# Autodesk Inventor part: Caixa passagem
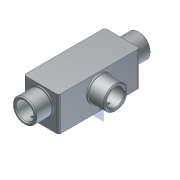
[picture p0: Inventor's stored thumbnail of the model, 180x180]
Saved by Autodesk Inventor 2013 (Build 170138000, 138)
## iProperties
Created: 2010-06
Part Number: Caixa passagem
Document SubType Name: Modeling
Designer: Usuario
Density: 1 g/cm^3
Material: Plástico PBT
Author: Usuario
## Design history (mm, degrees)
sketch "Sketch1"
  geometry: L1 (-20, 61.5)-(20, 61.5) reference; L2 (24.5, 57)-(24.5, -57) reference; L3 (20, -61.5)-(-20, -61.5) reference; L4 (-24.5, -57)-(-24.5, 57) reference; L5 (28, 61.5)-(28, -61.5) reference; L6 (-24.5, 65)-(24.5, 65) reference; L7 (-28, -61.5)-(-28, 61.5) reference; L8 (24.5, -65)-(-24.5, -65) reference; C1 r 2 at (-24.5, -61.5) reference; C2 r 2 at (24.5, -61.5) reference; C3 r 2 at (24.5, 61.5) reference; C4 r 2 at (-24.5, 61.5) reference; A1 r 4.5 centre (-24.5, 61.5) between (-24.5, 57) and (-20, 61.5) reference; A2 r 4.5 centre (24.5, 61.5) between (20, 61.5) and (24.5, 57) reference; A3 r 4.5 centre (24.5, -61.5) between (24.5, -57) and (20, -61.5) reference; A4 r 4.5 centre (-24.5, -61.5) between (-20, -61.5) and (-24.5, -57) reference; A5 r 3.5 centre (24.5, 61.5) between (28, 61.5) and (24.5, 65) reference; A6 r 3.5 centre (-24.5, 61.5) between (-24.5, 65) and (-28, 61.5) reference; A7 r 3.5 centre (-24.5, -61.5) between (-28, -61.5) and (-24.5, -65) reference; A8 r 3.5 centre (24.5, -61.5) between (24.5, -65) and (28, -61.5) reference; 1 further point
extrude "Extrusion1" new body sketch "Sketch1" distance "d0" = 55; taper "d1" = 0 deg
sketch "Sketch2"
  geometry: L1 (-20, 61.5)-(20, 61.5) reference; L2 (24.5, 57)-(24.5, -57) reference; L3 (20, -61.5)-(-20, -61.5) reference; L4 (-24.5, -57)-(-24.5, 57) reference; A1 r 4.5 centre (24.5, 61.5) between (20, 61.5) and (24.5, 57) reference; A2 r 4.5 centre (24.5, -61.5) between (24.5, -57) and (20, -61.5) reference; A3 r 4.5 centre (-24.5, -61.5) between (-20, -61.5) and (-24.5, -57) reference; A4 r 4.5 centre (-24.5, 61.5) between (-24.5, 57) and (-20, 61.5) reference; 1 further point
extrude "Extrusion2" join sketch "Sketch2" distance "d2" = 3.5; taper "d3" = 0 deg
sketch "Sketch3"
  geometry: A1 r 3.5 centre (-24.5, -61.5) between (-28, -61.5) and (-24.5, -65) reference; A2 r 3.5 centre (24.5, -61.5) between (24.5, -65) and (28, -61.5) reference; A3 r 3.5 centre (24.5, 61.5) between (28, 61.5) and (24.5, 65) reference; A4 r 3.5 centre (-24.5, 61.5) between (-24.5, 65) and (-28, 61.5) reference; 5 further points
  constraints: 4 coincident
hole "Hole1" sketch "Sketch3" diameter "d4" = 3.242; stored, may be unused: countersink angle "d8" = 90 deg, drill point angle "d10" = 118 deg; dims "d5" = 10, "d6" = 4, "d7" = 2, "d9" = 15
sketch "Sketch4"
  geometry: L1 (-55, 123)-(-55, 0) reference; L2 (0, -3.5)-(-55, -3.5) reference; L3 (0, 123)-(-55, 123) reference; L4 (-55, 61.5)-(14.676, 61.5); C1 r 10 at (-32, 61.5); 1 further point
  constraints: 2 end point, 1 centre point, 1 midpoint, 1 parallel, 1 point on line
  dimensions: "d11" = 20 diameter of C1; "d12" = 23 distance from line of L1 C1.centre
extrude "Extrusion3" cut sketch "Sketch4" distance "d14" = 3.5; taper "d15" = 0 deg
sketch "Sketch5"
  geometry: C1 r 10 at (-32, 61.5) reference; C2 r 19 at (-32, 61.5); C3 r 14 at (-32, 61.5); 1 further point
  constraints: 2 centre point, 2 coincident
  dimensions: "d16" = 38 diameter of C2; "d17" = 28 diameter of C3
extrude "Extrusion4" join sketch "Sketch5" distance "d18" = 27; taper "d19" = 0 deg
sketch "Sketch7"
  geometry: C1 r 19 at (-32, 61.5) reference; C2 r 20.5 at (-32, 61.5); 1 further point
  constraints: 1 centre point, 1 coincident
  dimensions: "d21" = 41 diameter of C2
extrude "Extrusion5" join sketch "Sketch7" distance "d22" = 2; taper "d23" = 0 deg
chamfer "Chamfer1" distance "d24" = 1.5; stored, may be unused: second distance "d25" = 2, angle "d26" = 45 deg
chamfer "Chamfer2" distance "d27" = 4; stored, may be unused: second distance "d28" = 2, angle "d29" = 45 deg
sketch "Sketch8"
  geometry: L1 (0, -55)-(49, -55) reference; C1 r 10 at (24.5, -32); 1 further point
  constraints: 1 centre point
  dimensions: "d30" = 23 distance from line of L1 C1.centre; "d31" = 20 diameter of C1
extrude "Extrusion6" cut sketch "Sketch8" distance "d32" = 3.5; taper "d33" = 0 deg
sketch "Sketch9"
  geometry: C1 r 10 at (24.5, -32) reference; C2 r 19 at (24.5, -32); C3 r 14 at (24.5, -32); 1 further point
  constraints: 2 centre point, 2 coincident
  dimensions: "d34" = 38 diameter of C2; "d35" = 28 diameter of C3
extrude "Extrusion7" join sketch "Sketch9" distance "d36" = 27; taper "d37" = 0 deg
sketch "Sketch10"
  geometry: C1 r 19 at (24.5, -32) reference; C2 r 20.5 at (24.5, -32); 1 further point
  constraints: 1 centre point, 1 coincident
  dimensions: "d38" = 41 diameter of C2
extrude "Extrusion8" join sketch "Sketch10" distance "d39" = 2; taper "d40" = 0 deg
chamfer "Chamfer3" distance "d41" = 1.5; stored, may be unused: second distance "d42" = 2, angle "d43" = 45 deg
chamfer "Chamfer4" distance "d44" = 4; stored, may be unused: second distance "d45" = 2, angle "d46" = 45 deg
workplane "Work Plane3"
  workplane "Work Plane1"
workplane "Work Plane4"
sketch "Sketch15"
  geometry: C1 r 10 at (24.5, 32) reference; 1 further point
extrude "Extrusion12" cut sketch "Sketch15" distance "d70" = 3.5; taper "d71" = 0 deg
sketch "Sketch16"
  geometry: C1 r 10 at (24.5, 32) reference; C2 r 14 at (24.5, 32); C3 r 19 at (24.5, 32); 1 further point
  constraints: 2 centre point, 2 coincident
  dimensions: "d72" = 28 diameter of C2; "d73" = 38 diameter of C3
extrude "Extrusion13" join sketch "Sketch16" distance "d74" = 27; taper "d75" = 0 deg
sketch "Sketch17"
  geometry: C1 r 19 at (24.5, 32) reference; C2 r 20.5 at (24.5, 32); 1 further point
  constraints: 1 centre point, 1 coincident
  dimensions: "d76" = 41 diameter of C2
extrude "Extrusion14" join sketch "Sketch17" distance "d77" = 2; taper "d78" = 0 deg
chamfer "Chamfer6" distance "d79" = 1.5; stored, may be unused: second distance "d80" = 2, angle "d81" = 45 deg
chamfer "Chamfer7" distance "d82" = 4; stored, may be unused: second distance "d83" = 2, angle "d84" = 45 deg
sketch "Sketch13"
  geometry: L1 (19, 2)-(-19, 2) reference; L2 (19, 25.5)-(-19, 25.5) reference; L3 (0, 25.5)-(0, 14.5); L4 (-30, -46)-(-30, -84) reference; L5 (-53.5, -46)-(-53.5, -84) reference; L6 (-53.5, -46)-(-53.5, -84) reference; L7 (-53.5, -65)-(-42.5, -65); C1 r 3 at (0, 14.5); C2 r 3 at (-42.5, -65); 1 further point
  constraints: 4 end point, 2 centre point, 2 coincident, 2 midpoint, 2 perpendicular
  dimensions: "d57" = 11 distance of L3.start L3.end; "d58" = 6 diameter of C1; "d61" = 11 distance of L7.start L7.end; "d62" = 6 diameter of C2
extrude "Extrusion10" join sketch "Sketch13" stored distance "d59" = 10; taper "d60" = 0 deg
sketch "Sketch14"
  geometry: C1 r 3 at (0, 0) reference; C2 r 2 at (0, 0); C3 r 3 at (-42.5, -79.5) reference; C4 r 2 at (-42.5, -79.5); 1 further point
  constraints: 2 centre point, 2 coincident
  dimensions: "d63" = 4 diameter of C2; "d64" = 4 diameter of C4
extrude "Extrusion11" cut sketch "Sketch14" distance "d65" = 10; taper "d66" = 0 deg
chamfer "Chamfer5" distance "d67" = 1; stored, may be unused: second distance "d68" = 2, angle "d69" = 45 deg
mirror "Mirror1"
chamfer "Chamfer8" distance "d85" = 1; stored, may be unused: second distance "d86" = 2, angle "d87" = 45 deg
body "Solid1"
node "Reference1"
node "Projected Loop3"
node "Projected Loop4"
node "Projected Loop5"
other parameters: "d56" = 1.5
